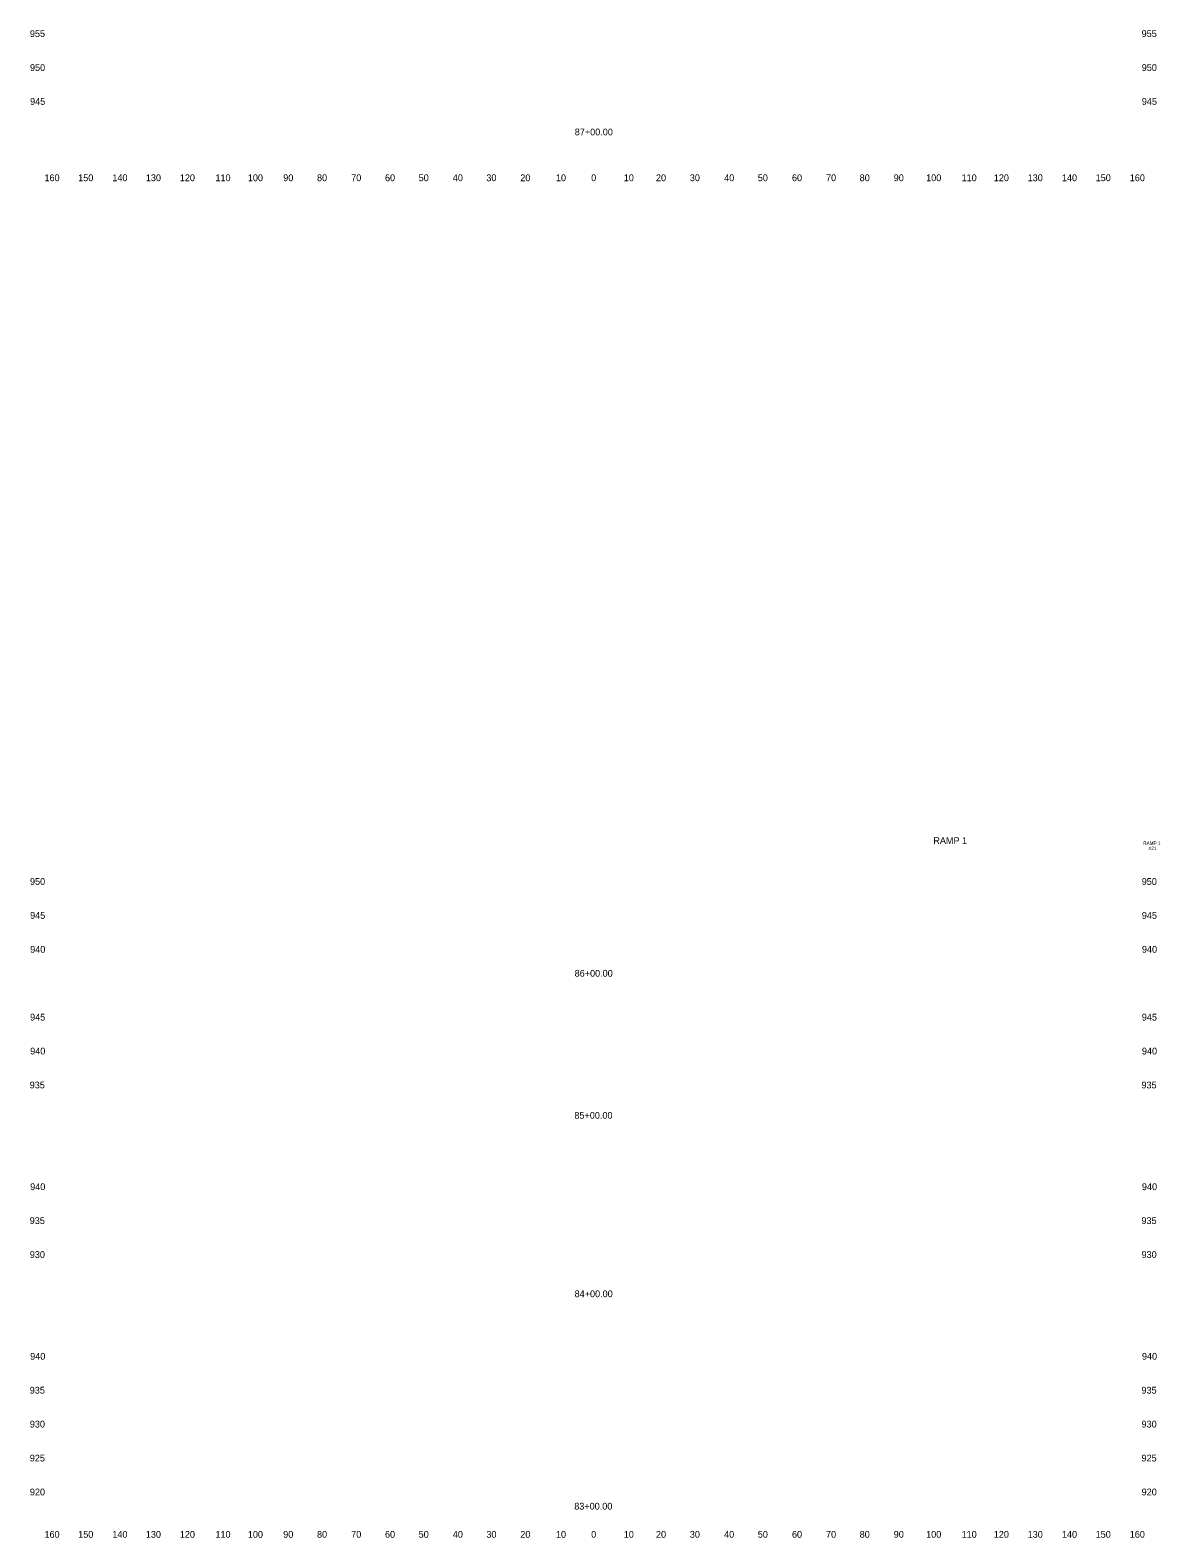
# Model space of a CAD drawing. Extents: x 4994 to 7869, y 4997 to 8804.
# Drawn here: x 6023.9 to 6357, y 4997.5 to 5442 of the extents above; entities that cross this region are included whole.
import ezdxf

# ---------------------------------------------------------------- set-up
doc = ezdxf.new("R2010")
doc.units = 0
for name, color, linetype in [('RD_SHT_ID', 7, 'Continuous'), ('RD_XS_TX_Offset', 7, 'Continuous'), ('RD_XS_TX_Station', 7, 'Continuous')]:
    doc.layers.add(name, color=color, linetype=linetype)

msp = doc.modelspace()

# ---------------------------------------------------------------- texts
at = {"layer": 'RD_SHT_ID'}
for s, height, p in [('RAMP 1', 2, (6290.19, 5202.06)), ('RAMP 1', 1, (6352.06, 5201.8)), ('X21', 1, (6353.57, 5200.3))]:
    msp.add_text(s, height=height, dxfattribs=at).set_placement(p)
at = {"layer": 'RD_XS_TX_Offset'}
for s, p in [('955', (6023.8, 5440)), ('955', (6351.6, 5440)), ('950', (6023.83, 5430)), ('950', (6351.63, 5430)), ('945', (6023.86, 5420)), ('945', (6351.66, 5420)), ('160', (6028.1, 5397.5)), ('150', (6038.04, 5397.5)), ('140', (6048.1, 5397.5)), ('130', (6057.99, 5397.5)), ('120', (6068.01, 5397.5)), ('110', (6078.51, 5397.5)), ('100', (6088.07, 5397.5)), ('90', (6098.5, 5397.5)), ('80', (6108.46, 5397.5)), ('70', (6118.54, 5397.5)), ('60', (6128.5, 5397.5)), ('50', (6138.43, 5397.5)), ('40', (6148.5, 5397.5)), ('30', (6158.39, 5397.5)), ('20', (6168.4, 5397.5)), ('10', (6178.91, 5397.5)), ('0', (6189.3, 5397.5)), ('0', (6189.3, 5397.5)), ('10', (6198.91, 5397.5)), ('20', (6208.4, 5397.5)), ('30', (6218.39, 5397.5)), ('40', (6228.5, 5397.5)), ('50', (6238.43, 5397.5)), ('60', (6248.5, 5397.5)), ('70', (6258.54, 5397.5)), ('80', (6268.46, 5397.5)), ('90', (6278.5, 5397.5)), ('100', (6288.07, 5397.5)), ('110', (6298.51, 5397.5)), ('120', (6308.01, 5397.5)), ('130', (6317.99, 5397.5)), ('140', (6328.1, 5397.5)), ('150', (6338.04, 5397.5)), ('160', (6348.1, 5397.5)), ('950', (6023.83, 5190)), ('950', (6351.63, 5190)), ('945', (6023.86, 5180)), ('945', (6351.66, 5180)), ('940', (6023.89, 5170)), ('940', (6351.69, 5170)), ('945', (6023.86, 5150)), ('945', (6351.66, 5150)), ('940', (6023.89, 5140)), ('940', (6351.69, 5140)), ('935', (6023.75, 5130)), ('935', (6351.55, 5130)), ('940', (6023.89, 5100)), ('940', (6351.69, 5100)), ('935', (6023.75, 5090)), ('935', (6351.55, 5090)), ('930', (6023.78, 5080)), ('930', (6351.58, 5080)), ('940', (6023.89, 5050)), ('940', (6351.69, 5050)), ('935', (6023.75, 5040)), ('935', (6351.55, 5040)), ('930', (6023.78, 5030)), ('930', (6351.58, 5030)), ('925', (6023.77, 5020)), ('925', (6351.57, 5020)), ('920', (6023.8, 5010)), ('920', (6351.6, 5010)), ('160', (6028.1, 4997.5)), ('150', (6038.04, 4997.5)), ('140', (6048.1, 4997.5)), ('130', (6057.99, 4997.5)), ('120', (6068.01, 4997.5)), ('110', (6078.51, 4997.5)), ('100', (6088.07, 4997.5)), ('90', (6098.5, 4997.5)), ('80', (6108.46, 4997.5)), ('70', (6118.54, 4997.5)), ('60', (6128.5, 4997.5)), ('50', (6138.43, 4997.5)), ('40', (6148.5, 4997.5)), ('30', (6158.39, 4997.5)), ('20', (6168.4, 4997.5)), ('10', (6178.91, 4997.5)), ('0', (6189.3, 4997.5)), ('0', (6189.3, 4997.5)), ('10', (6198.91, 4997.5)), ('20', (6208.4, 4997.5)), ('30', (6218.39, 4997.5)), ('40', (6228.5, 4997.5)), ('50', (6238.43, 4997.5)), ('60', (6248.5, 4997.5)), ('70', (6258.54, 4997.5)), ('80', (6268.46, 4997.5)), ('90', (6278.5, 4997.5)), ('100', (6288.07, 4997.5)), ('110', (6298.51, 4997.5)), ('120', (6308.01, 4997.5)), ('130', (6317.99, 4997.5)), ('140', (6328.1, 4997.5)), ('150', (6338.04, 4997.5)), ('160', (6348.1, 4997.5))]:
    msp.add_text(s, height=2, dxfattribs=at).set_placement(p)
at = {"layer": 'RD_XS_TX_Station'}
for s, p in [('87+00.00', (6184.46, 5411.01)), ('86+00.00', (6184.42, 5162.93)), ('85+00.00', (6184.35, 5121.05)), ('84+00.00', (6184.42, 5068.43)), ('83+00.00', (6184.31, 5005.8))]:
    msp.add_text(s, height=2, dxfattribs=at).set_placement(p)

doc.saveas('drawing.dxf')
